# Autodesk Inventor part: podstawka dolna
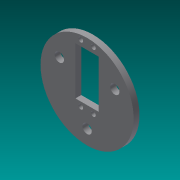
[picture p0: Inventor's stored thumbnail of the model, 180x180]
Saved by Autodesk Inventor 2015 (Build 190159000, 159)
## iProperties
Created: 2016-02
Part Number: podstawka dolna
Material: Generic
Document SubType Name: Modeling
Designer: Rafał
Density: 1 g/cm^3
Appearance: Default
Author: Rafał
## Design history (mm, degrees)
sketch "Sketch1" dims "d9" = 55
  geometry: L1 (0, 0)-(5.4, 0); L2 (5.4, 0)-(5.4, -13.9); L3 (5.4, 0)-(5.4, 35.9); L4 (0, 0)-(0, 11.296); L5 (0, 0)-(10, 0); L6 (10, 0)-(10, 31); L7 (10, 0)-(10, -10); L8 (10, -10)-(0, -10); L9 (10, 31)-(0, 31); L10 (-10, 31)-(0, 31); L11 (-10, 0)-(-10, 31); L12 (-10, 0)-(-10, -10); L13 (-10, -10)-(0, -10); L14 (0, 0)-(0, -35.729); C1 r 2 at (5.4, 35.9); C2 r 2 at (5.4, -13.9); C3 r 2 at (-5.4, 35.9); C4 r 2 at (-5.4, -13.9); C5 r 40 at (0, 0); C6 r 4 at (0, -27.5); C7 r 4 at (23.816, 13.75); C8 r 4 at (-23.816, 13.75); 3 further points
  constraints: 28 end point, 8 centre point, 7 symmetric about line, 6 coincident, 4 vertical, 3 horizontal, 3 perpendicular, 1 point on line, 1 vertical alignment, 11 other
  dimensions: "d0" = 5.4 distance of L1.start L1.end; "d1" = 13.9 distance of L1.end L2.end; "d2" = 35.9 distance of L1.end L3.end; "d3" = 4 diameter of C1; "d4" = 4 diameter of C2; "d5" = 10 distance of L1.start L5.end; "d6" = 31 distance of L5.end L6.end; "d7" = 10 distance of L5.end L7.end; "d8" = 80 diameter of C5; "d10" = 8 diameter of C6; "d13" = 360 deg dimension on L1.start C6.centre (derived)
extrude "Extrusion1" new body sketch "Sketch1" distance "d15" = 5; taper "d16" = 0 deg
body "Solid1"
